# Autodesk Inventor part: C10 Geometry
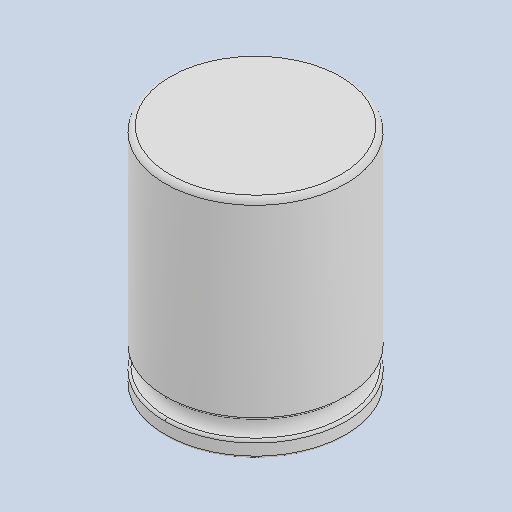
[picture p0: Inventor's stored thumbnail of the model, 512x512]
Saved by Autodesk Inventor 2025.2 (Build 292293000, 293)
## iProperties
Created: 2025-04
Part Number: C10 Geometry
Material: Generic
Description: PART-C10 Geometry-DESC
Document SubType Name: Modeling
Designer: BennF
Density: 1 g/cm^3
Appearance: Default
Author: BennF
Revision Number: NONE
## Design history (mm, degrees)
feature "Solid"
body "Solid1"
